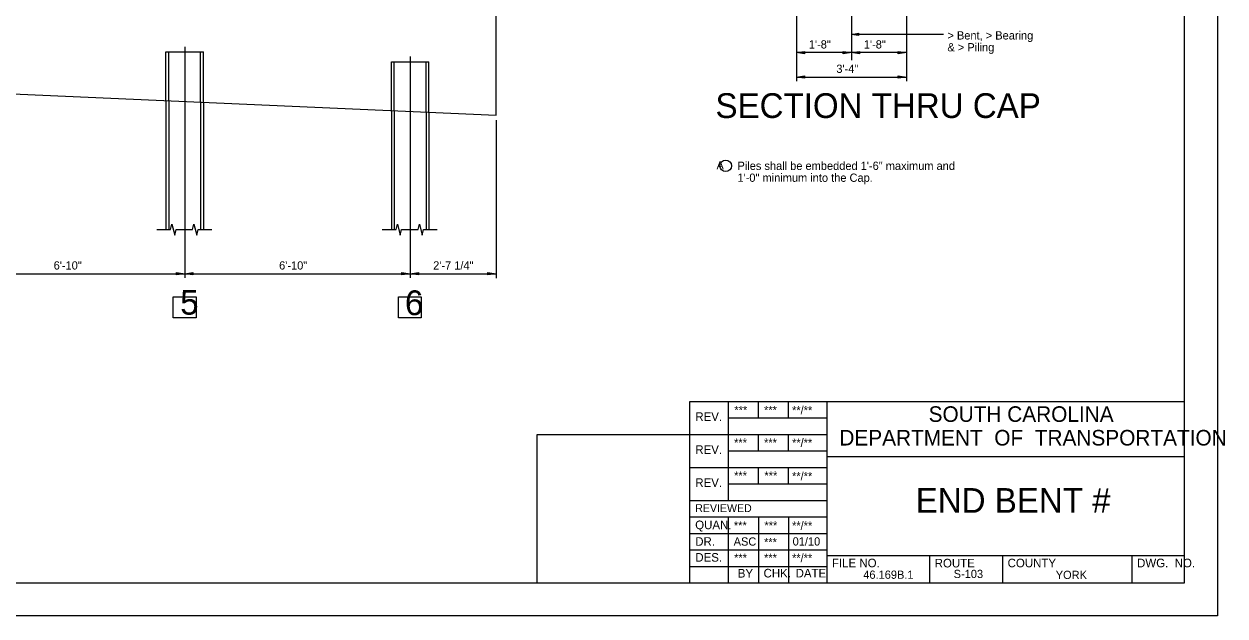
# Model space of a CAD drawing. Extents: x -470 to -397.8, y 402.4 to 446.4.
# Drawn here: x -434.18 to -397.78, y 402.38 to 420.31 of the extents above; entities that cross this region are included whole.
import ezdxf

# ---------------------------------------------------------------- set-up
doc = ezdxf.new("R2010")
doc.units = 0
for name, color, linetype in [('BR_AUTO DIMENSION', 7, 'Continuous'), ('BR_BORDER LINES', 7, 'Continuous'), ('BR_CENTER LINES', 7, 'Continuous'), ('BR_CONCRETE', 7, 'Continuous'), ('BR_REBAR', 7, 'Continuous'), ('BR_TEXT', 7, 'Continuous'), ('RD_SHT_IplotShp', 7, 'Continuous')]:
    doc.layers.add(name, color=color, linetype=linetype)

msp = doc.modelspace()

# ---------------------------------------------------------------- linework, layer by layer
at = {"layer": 'BR_AUTO DIMENSION'}
for p, q in [((-410.769, 422.291), (-410.769, 419.323)), ((-407.436, 422.291), (-407.436, 419.323)), ((-406.308, 420.002), (-409.094, 420.002)), ((-407.436, 419.448), (-410.769, 419.448)), ((-410.769, 419.323), (-410.769, 418.584)), ((-407.436, 419.323), (-407.436, 418.584)), ((-410.769, 418.709), (-407.436, 418.709)), ((-419.874, 417.407), (-419.874, 412.61)), ((-430.155, 414.089), (-429.738, 414.089)), ((-429.738, 414.089), (-429.697, 414.256)), ((-429.697, 414.256), (-429.613, 413.922)), ((-429.613, 413.922), (-429.572, 414.089)), ((-429.572, 414.089), (-429.072, 414.089)), ((-429.072, 414.089), (-429.03, 414.256)), ((-429.03, 414.256), (-428.946, 413.922)), ((-428.946, 413.922), (-428.905, 414.089)), ((-428.905, 414.089), (-428.488, 414.089)), ((-423.322, 414.089), (-422.905, 414.089)), ((-422.905, 414.089), (-422.863, 414.256)), ((-422.863, 414.256), (-422.78, 413.922)), ((-422.78, 413.922), (-422.738, 414.089)), ((-422.738, 414.089), (-422.238, 414.089)), ((-422.238, 414.089), (-422.197, 414.256)), ((-422.197, 414.256), (-422.113, 413.922)), ((-422.113, 413.922), (-422.071, 414.089)), ((-422.071, 414.089), (-421.655, 414.089)), ((-429.311, 413.236), (-429.311, 412.626)), ((-422.478, 413.236), (-422.478, 412.626)), ((-436.145, 412.751), (-429.311, 412.751)), ((-429.311, 412.751), (-422.478, 412.751)), ((-422.478, 412.751), (-419.874, 412.751))]:
    msp.add_line(p, q, dxfattribs=at)
for points in [[(-408.883, 419.971), (-409.103, 420), (-408.884, 420.038)], [(-410.519, 419.41), (-410.769, 419.448), (-410.519, 419.485)], [(-409.353, 419.485), (-409.103, 419.448), (-409.353, 419.41)], [(-408.853, 419.41), (-409.103, 419.448), (-408.853, 419.485)], [(-407.686, 419.485), (-407.436, 419.448), (-407.686, 419.41)], [(-410.519, 418.671), (-410.769, 418.709), (-410.519, 418.746)], [(-407.686, 418.746), (-407.436, 418.709), (-407.686, 418.671)], [(-429.561, 412.789), (-429.311, 412.751), (-429.561, 412.714)], [(-429.061, 412.714), (-429.311, 412.751), (-429.061, 412.789)], [(-422.728, 412.789), (-422.478, 412.751), (-422.728, 412.714)], [(-422.228, 412.714), (-422.478, 412.751), (-422.228, 412.789)], [(-420.124, 412.789), (-419.874, 412.751), (-420.124, 412.714)]]:
    msp.add_lwpolyline(points, close=True, dxfattribs=at)
at = {"layer": 'BR_BORDER LINES'}
for p, q in [((-399.004, 403.38), (-399.004, 445.38)), ((-414.004, 408.88), (-399.004, 408.88)), ((-414.004, 403.38), (-414.004, 408.88)), ((-412.837, 408.88), (-412.837, 405.88)), ((-411.92, 408.38), (-411.92, 408.88)), ((-411.004, 408.38), (-411.004, 408.88)), ((-409.837, 403.38), (-409.837, 408.88)), ((-412.837, 408.38), (-409.837, 408.38)), ((-418.629, 407.88), (-414.004, 407.88)), ((-418.629, 403.38), (-418.629, 407.88)), ((-414.004, 407.88), (-409.837, 407.88)), ((-411.92, 407.38), (-411.92, 407.88)), ((-411.004, 407.38), (-411.004, 407.88)), ((-412.837, 407.38), (-409.837, 407.38)), ((-409.837, 407.213), (-399.004, 407.213)), ((-409.837, 407.213), (-409.837, 407.213)), ((-399.004, 407.213), (-399.004, 407.213)), ((-414.004, 406.88), (-409.837, 406.88)), ((-411.92, 406.38), (-411.92, 406.88)), ((-411.004, 406.38), (-411.004, 406.88)), ((-412.837, 406.38), (-409.837, 406.38)), ((-414.004, 405.88), (-409.837, 405.88)), ((-414.004, 405.38), (-409.837, 405.38)), ((-412.837, 405.38), (-412.837, 403.38)), ((-411.92, 405.38), (-411.92, 403.38)), ((-411.004, 405.38), (-411.004, 403.38)), ((-414.004, 404.88), (-409.837, 404.88)), ((-414.004, 404.38), (-409.837, 404.38)), ((-409.837, 404.213), (-399.004, 404.213)), ((-406.723, 403.38), (-406.723, 404.213)), ((-404.514, 403.38), (-404.514, 404.213)), ((-400.594, 403.38), (-400.594, 404.213)), ((-414.004, 403.88), (-409.837, 403.88)), ((-466.337, 403.38), (-399.004, 403.38))]:
    msp.add_line(p, q, dxfattribs=at)
at = {"layer": 'BR_CENTER LINES'}
for p, q in [((-409.103, 433.394), (-409.103, 419.225)), ((-429.311, 419.629), (-429.311, 413.236)), ((-422.478, 419.328), (-422.478, 413.236))]:
    msp.add_line(p, q, dxfattribs=at)
at = {"layer": 'BR_CONCRETE'}
msp.add_line((-459.249, 419.29), (-419.874, 417.558), dxfattribs=at)
at = {"layer": 'BR_REBAR'}
for p, q in [((-419.874, 417.558), (-419.874, 420.558)), ((-429.879, 419.473), (-428.743, 419.473)), ((-429.879, 417.998), (-429.879, 419.473)), ((-429.795, 417.995), (-429.795, 419.473)), ((-428.827, 417.952), (-428.827, 419.473)), ((-428.743, 417.948), (-428.743, 419.473)), ((-423.045, 419.173), (-421.91, 419.173)), ((-423.045, 417.698), (-423.045, 419.173)), ((-422.962, 417.694), (-422.962, 419.173)), ((-421.993, 417.651), (-421.993, 419.173)), ((-421.91, 417.648), (-421.91, 419.173)), ((-429.879, 417.998), (-429.879, 414.089)), ((-429.795, 417.995), (-429.795, 414.089)), ((-428.827, 417.952), (-428.827, 414.089)), ((-428.743, 417.948), (-428.743, 414.089)), ((-423.045, 417.698), (-423.045, 414.089)), ((-422.962, 417.694), (-422.962, 414.089)), ((-421.993, 417.651), (-421.993, 414.089)), ((-421.91, 417.648), (-421.91, 414.089))]:
    msp.add_line(p, q, dxfattribs=at)
at = {"layer": 'BR_TEXT'}
for points in [[(-429.656, 412.046), (-428.963, 412.046), (-428.963, 411.41), (-429.656, 411.41)], [(-422.835, 412.046), (-422.142, 412.046), (-422.142, 411.41), (-422.835, 411.41)]]:
    msp.add_lwpolyline(points, close=True, dxfattribs=at)
msp.add_circle((-412.912, 416.02), 0.175, dxfattribs=at)
at = {"layer": 'RD_SHT_IplotShp'}
for p, q in [((-398.003, 446.38), (-398.003, 402.38)), ((-398.003, 402.38), (-470.003, 402.38))]:
    msp.add_line(p, q, dxfattribs=at)

# ---------------------------------------------------------------- texts
at = {"layer": 'BR_TEXT'}
for s, height, p in [('> Bent, > Bearing', 0.25, (-406.192, 419.846)), ('1\'-8"', 0.25, (-410.393, 419.573)), ('1\'-8"', 0.25, (-408.726, 419.573)), ('& > Piling', 0.25, (-406.192, 419.486)), ('3\'-4"', 0.25, (-409.559, 418.834)), ('SECTION THRU CAP', 0.75, (-413.223, 417.468)), ('  A', 0.25, (-413.378, 415.908)), ('Piles shall be embedded 1\'-6" maximum and ', 0.25, (-412.556, 415.895)), ('1\'-0" minimum into the Cap.   ', 0.25, (-412.556, 415.534)), ('6\'-10"', 0.25, (-433.283, 412.876)), ('6\'-10"', 0.25, (-426.449, 412.876)), ('2\'-7 1/4"', 0.25, (-421.78, 412.876)), ('5', 0.75, (-429.447, 411.509)), ('6', 0.75, (-422.635, 411.495)), ('REV.', 0.26, (-413.834, 408.291)), ('***', 0.25, (-412.649, 408.494)), ('***', 0.25, (-411.751, 408.494)), ('**/**', 0.25, (-410.902, 408.488)), ('SOUTH CAROLINA', 0.4717, (-406.762, 408.261)), ('***', 0.25, (-412.658, 407.508)), ('***', 0.25, (-411.751, 407.508)), ('**/**', 0.25, (-410.902, 407.504)), ('DEPARTMENT  OF  TRANSPORTATION', 0.4717, (-409.467, 407.545)), ('REV.', 0.26, (-413.834, 407.291)), ('***', 0.25, (-412.658, 406.509)), ('***', 0.25, (-411.739, 406.509)), ('**/**', 0.25, (-410.902, 406.49)), ('REV.', 0.26, (-413.834, 406.291)), ('END BENT # ', 0.75, (-407.153, 405.505)), ('REVIEWED', 0.24, (-413.836, 405.527)), ('QUAN.', 0.26, (-413.837, 405.01)), ('***', 0.25, (-412.665, 404.998)), ('***', 0.25, (-411.739, 404.998)), ('**/**', 0.25, (-410.902, 404.993)), ('DR.', 0.26, (-413.836, 404.507)), ('ASC', 0.25, (-412.672, 404.511)), ('***', 0.25, (-411.75, 404.491)), ('01/10', 0.25, (-410.884, 404.514)), ('DES.', 0.26, (-413.834, 404.025)), ('***', 0.25, (-412.658, 404.017)), ('***', 0.25, (-411.75, 404.017)), ('**/**', 0.25, (-410.902, 404.013)), ('FILE NO.', 0.26, (-409.692, 403.855)), ('ROUTE', 0.26, (-406.578, 403.851)), ('COUNTY', 0.26, (-404.367, 403.855)), ('DWG.  NO.', 0.26, (-400.443, 403.855)), ('BY', 0.26, (-412.546, 403.544)), ('CHK.', 0.26, (-411.765, 403.547)), ('DATE', 0.26, (-410.794, 403.547)), ('46.169B.1', 0.25, (-408.743, 403.506)), ('S-103', 0.25, (-406.003, 403.529)), ('YORK', 0.25, (-402.909, 403.5))]:
    msp.add_text(s, height=height, dxfattribs=at).set_placement(p)

doc.saveas('drawing.dxf')
